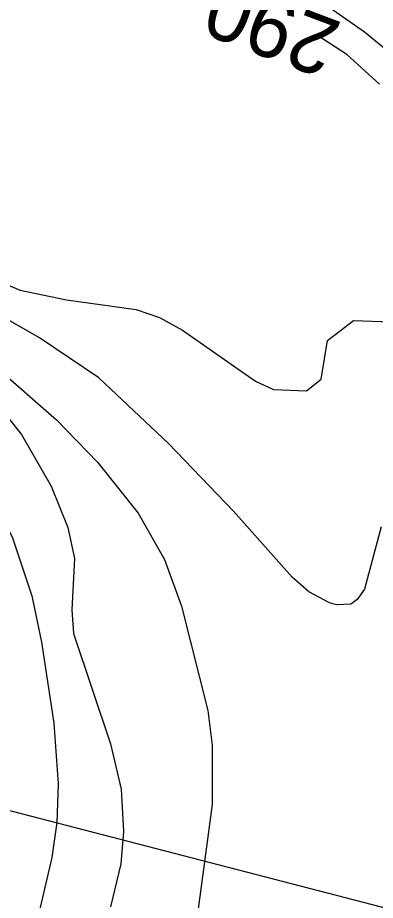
# Model space of a CAD drawing. Extents: x -662620 to -656370, y -1067090 to -1062990.
# Drawn here: x -660189.8 to -660110.3, y -1066298.9 to -1066102.6 of the extents above; entities that cross this region are included whole.
import ezdxf

# ---------------------------------------------------------------- set-up
doc = ezdxf.new("R2010")
doc.units = 0
for name, color, linetype in [('CHRANENE_LOZISKOVE_UZEMI', 7, 'Continuous'), ('VRSTEVNICE_ZDŮRAZNĚNÁ', 7, 'Continuous'), ('VRSTEVNICE_ZDŮRAZNĚNÁ_-_POPIS', 7, 'Continuous'), ('VRSTEVNICE_ZÁKLADNÍ', 7, 'Continuous')]:
    doc.layers.add(name, color=color, linetype=linetype)

msp = doc.modelspace()

# ---------------------------------------------------------------- linework, layer by layer
at = {"layer": 'CHRANENE_LOZISKOVE_UZEMI'}
msp.add_lwpolyline([(-659950.49, -1066341.51), (-660241.1, -1066266.15), (-660233.3, -1066253.72), (-660230.22, -1066239.29), (-660242.05, -1066228.88), (-660267.73, -1066231.4), (-660289.72, -1066216.1), (-660294.62, -1066209.1), (-660303.95, -1066205.07), (-660327.62, -1066210.77), (-660366.47, -1066201.31)], dxfattribs=at)
at = {"layer": 'VRSTEVNICE_ZDŮRAZNĚNÁ'}
for points in [[(-660109.36, -1066117.36), (-660116.61, -1066110.76), (-660122.92, -1066106.74)], [(-660254.32, -1066112.47), (-660250.7, -1066120.17), (-660244.34, -1066129.09), (-660210.61, -1066152.48), (-660199.58, -1066158.93), (-660189.26, -1066163.23), (-660178.94, -1066165.38), (-660163.46, -1066167.53), (-660158.3, -1066169.25), (-660153.14, -1066172.11), (-660136.95, -1066183.44), (-660132.93, -1066185.3), (-660125.62, -1066185.58), (-660122.33, -1066183.01), (-660120.9, -1066174.41), (-660115.15, -1066169.93), (-660102.69, -1066170.39), (-660097.54, -1066169.39), (-660094.43, -1066164.71), (-660094.53, -1066158.93), (-660096.6, -1066153.06), (-660102.81, -1066145.16)]]:
    msp.add_lwpolyline(points, dxfattribs=at)
at = {"layer": 'VRSTEVNICE_ZÁKLADNÍ'}
for points in [[(-660145.17, -1066086.08), (-660135.29, -1066090.95), (-660122.76, -1066098.59), (-660112.73, -1066105.76), (-660094.67, -1066120.52)], [(-660145.17, -1066086.08), (-660135.29, -1066090.95), (-660122.76, -1066098.59), (-660112.73, -1066105.76), (-660094.67, -1066120.52)], [(-660365.02, -1066102.99), (-660328.9, -1066111.73), (-660322.69, -1066113.93), (-660320.25, -1066114.79), (-660296.75, -1066122.24), (-660280.69, -1066128.4), (-660268.66, -1066133.7), (-660252.6, -1066142.16), (-660228.81, -1066157.93), (-660212.76, -1066170.82), (-660203.59, -1066178.85), (-660196.71, -1066185.73), (-660188.97, -1066195.33), (-660182.38, -1066206.8), (-660178.65, -1066215.97), (-660177.22, -1066222.85), (-660177.79, -1066234.31), (-660177.45, -1066239.6), (-660169.19, -1066264.12), (-660166.78, -1066274.22), (-660166.33, -1066283.61), (-660166.9, -1066290.78), (-660169.19, -1066300.38)], [(-660365.02, -1066102.99), (-660328.9, -1066111.73), (-660322.69, -1066113.93), (-660320.25, -1066114.79), (-660296.75, -1066122.24), (-660280.69, -1066128.4), (-660268.66, -1066133.7), (-660252.6, -1066142.16), (-660228.81, -1066157.93), (-660212.76, -1066170.82), (-660203.59, -1066178.85), (-660196.71, -1066185.73), (-660188.97, -1066195.33), (-660182.38, -1066206.8), (-660178.65, -1066215.97), (-660177.22, -1066222.85), (-660177.79, -1066234.31), (-660177.45, -1066239.6), (-660169.19, -1066264.12), (-660166.78, -1066274.22), (-660166.33, -1066283.61), (-660166.9, -1066290.78), (-660169.19, -1066300.38)], [(-660109, -1066215.83), (-660112.73, -1066229.73), (-660114.3, -1066232.02), (-660115.74, -1066233.02), (-660118.89, -1066233.17), (-660120.47, -1066232.74), (-660125.05, -1066230.3), (-660128.78, -1066227), (-660141.82, -1066212.39), (-660156.29, -1066197.34), (-660171.77, -1066182.72), (-660184.96, -1066173.83), (-660206.74, -1066161.36), (-660260.34, -1066125.25), (-660279.4, -1066114.07), (-660283.85, -1066111.92), (-660293.88, -1066108.34), (-660309.93, -1066105.9), (-660333.58, -1066104.61), (-660341.64, -1066102.6)], [(-660109, -1066215.83), (-660112.73, -1066229.73), (-660114.3, -1066232.02), (-660115.74, -1066233.02), (-660118.89, -1066233.17), (-660120.47, -1066232.74), (-660125.05, -1066230.3), (-660128.78, -1066227), (-660141.82, -1066212.39), (-660156.29, -1066197.34), (-660171.77, -1066182.72), (-660184.96, -1066173.83), (-660206.74, -1066161.36), (-660260.34, -1066125.25), (-660279.4, -1066114.07), (-660283.85, -1066111.92), (-660293.88, -1066108.34), (-660309.93, -1066105.9), (-660333.58, -1066104.61), (-660341.64, -1066102.6)], [(-660348.52, -1066104.64), (-660325.77, -1066109.31), (-660307.64, -1066112.35), (-660294.74, -1066116.08), (-660284.42, -1066120.38), (-660263.78, -1066132.13), (-660252.03, -1066137.86), (-660238.27, -1066145.89), (-660229.1, -1066152.19), (-660207.32, -1066170.54), (-660194.99, -1066180), (-660181.23, -1066192.03), (-660172.06, -1066201.49), (-660163.03, -1066212.82), (-660157.15, -1066223.13), (-660153.43, -1066233.45), (-660147.55, -1066256.67), (-660146.55, -1066264.41), (-660146.55, -1066277.59), (-660149.7, -1066300.81)], [(-660348.52, -1066104.64), (-660325.77, -1066109.31), (-660307.64, -1066112.35), (-660294.74, -1066116.08), (-660284.42, -1066120.38), (-660263.78, -1066132.13), (-660252.03, -1066137.86), (-660238.27, -1066145.89), (-660229.1, -1066152.19), (-660207.32, -1066170.54), (-660194.99, -1066180), (-660181.23, -1066192.03), (-660172.06, -1066201.49), (-660163.03, -1066212.82), (-660157.15, -1066223.13), (-660153.43, -1066233.45), (-660147.55, -1066256.67), (-660146.55, -1066264.41), (-660146.55, -1066277.59), (-660149.7, -1066300.81)], [(-660346.76, -1066116.08), (-660334.77, -1066118.26), (-660313.66, -1066124.68), (-660293.02, -1066132.84), (-660269.8, -1066141.16), (-660255.18, -1066147.61), (-660243.72, -1066153.63), (-660236.84, -1066158.36), (-660220.79, -1066171.83), (-660213.76, -1066179.57), (-660208.03, -1066187.31), (-660197.43, -1066205.36), (-660190.98, -1066218.26), (-660186.68, -1066231.16), (-660184.53, -1066241.48), (-660181.81, -1066259.54), (-660180.8, -1066273.01), (-660181.09, -1066281.61), (-660182.24, -1066289.35), (-660186.15, -1066306.19)], [(-660346.76, -1066116.08), (-660334.77, -1066118.26), (-660313.66, -1066124.68), (-660293.02, -1066132.84), (-660269.8, -1066141.16), (-660255.18, -1066147.61), (-660243.72, -1066153.63), (-660236.84, -1066158.36), (-660220.79, -1066171.83), (-660213.76, -1066179.57), (-660208.03, -1066187.31), (-660197.43, -1066205.36), (-660190.98, -1066218.26), (-660186.68, -1066231.16), (-660184.53, -1066241.48), (-660181.81, -1066259.54), (-660180.8, -1066273.01), (-660181.09, -1066281.61), (-660182.24, -1066289.35), (-660186.15, -1066306.19)]]:
    msp.add_lwpolyline(points, dxfattribs=at)

# ---------------------------------------------------------------- texts
at = {"layer": 'VRSTEVNICE_ZDŮRAZNĚNÁ_-_POPIS'}
msp.add_text('290', height=13.2, rotation=159.4047, dxfattribs=at).set_placement((-660117.29, -1066103.84))

doc.saveas('drawing.dxf')
